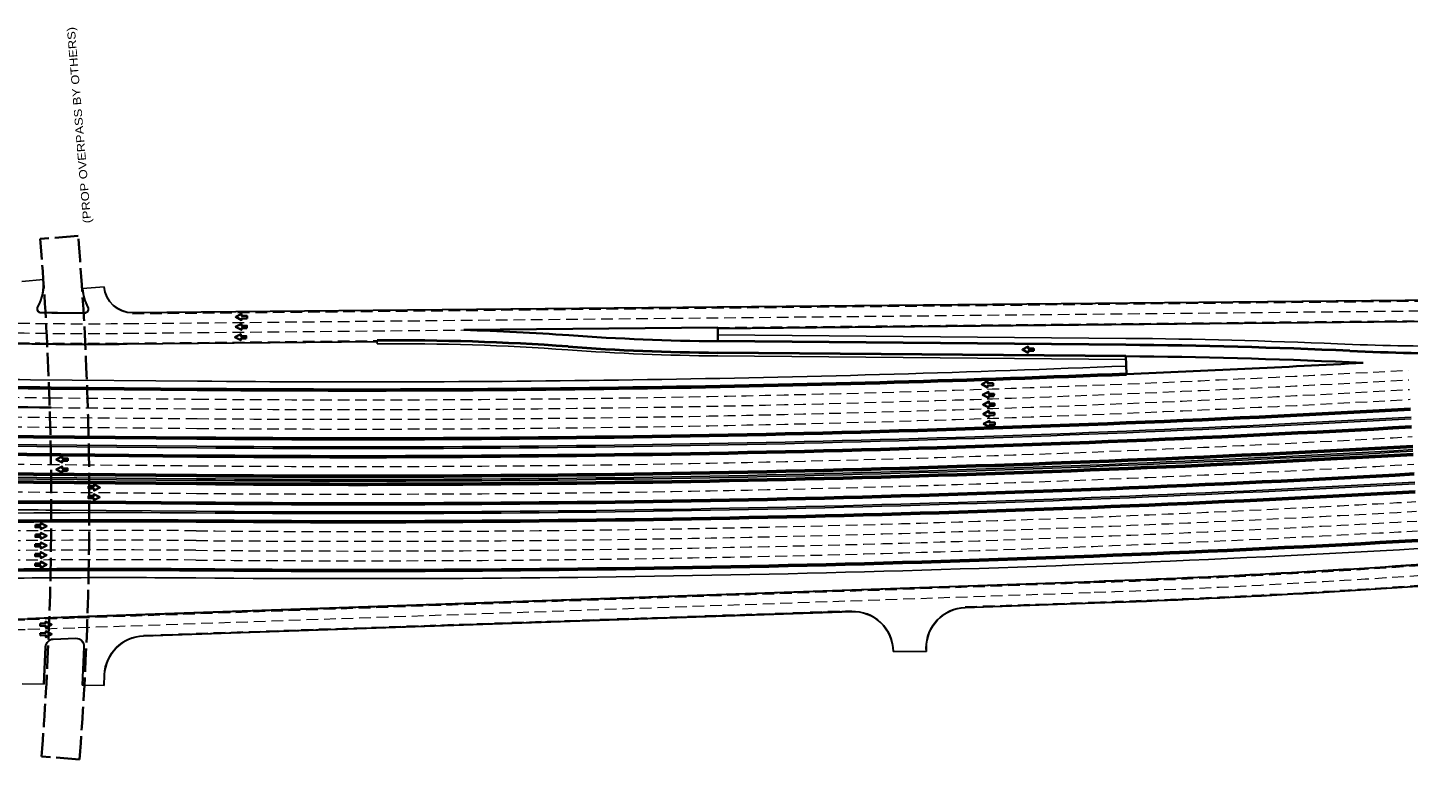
# Model space of a CAD drawing. Extents: x 2326434 to 2368642, y 6985225 to 6995090.
# Drawn here: x 2337174 to 2338872, y 6990920 to 6991821 of the extents above; entities that cross this region are included whole.
import ezdxf

# ---------------------------------------------------------------- set-up
doc = ezdxf.new("R2010")
doc.units = 0
doc.header["$LTSCALE"] = 4.8
doc.linetypes.add('LONG_DASHED', pattern=[7.5, 6, -1.5])
doc.linetypes.add('MEDIUM_DASHED', pattern=[4.5, 3, -1.5])
for name, color, linetype, lineweight in [('10', 7, 'Continuous', 35), ('20', 7, 'LONG_DASHED', 35), ('26', 7, 'Continuous', 25), ('27', 7, 'Continuous', 25), ('28', 7, 'Continuous', 25), ('30', 7, 'Continuous', 25), ('40', 7, 'Continuous', 35), ('50', 7, 'MEDIUM_DASHED', 13)]:
    doc.layers.add(name, color=color, linetype=linetype, lineweight=lineweight)

msp = doc.modelspace()

# ---------------------------------------------------------------- linework, layer by layer
at = {"layer": '10'}
for p, q in [((2337710.319, 6991448.663), (2338022.416, 6991451.725)), ((2338022.416, 6991451.725), (2338022.583, 6991434.726)), ((2338524.406, 6991416.353), (2338525.316, 6991394.372)), ((2336756.625, 6991357.064), (2337202.249, 6991353.214))]:
    msp.add_line(p, q, dxfattribs=at)
for centre, radius, start, end in [((2337631.381, 6988584.962), 2864.789, 85.83473, 88.42104), ((2338047.541, 6994299.406), 2864.789, 265.83473, 269.50083), ((2338457.973, 6983791.205), 7625.437, 87.43444, 89.50083), ((2337579.809, 7014229.636), 22854.83, 272.37101, 273.10141), ((2338946.487, 6994693.748), 3288.044, 267.43444, 267.73144), ((2337227.445, 6994241.893), 2888.789, 264.99101, 269.50502)]:
    msp.add_arc(centre, radius, start, end, dxfattribs=at)
at = {"layer": '20'}
for p, q in [((2337235.759, 6991564.563), (2337189.112, 6991560.708)), ((2337237.485, 6990920.494), (2337190.819, 6990924.099))]:
    msp.add_line(p, q, dxfattribs=at)
for radius in [4041.658, 3994.852]:
    msp.add_arc((2333207.829, 6991231.728), radius, 355.58348, 4.72371, dxfattribs=at)
at = {"layer": '26'}
for p, q in [((2337177.257, 6991387.431), (2337382.455, 6991385.658)), ((2336698.283, 6991311.566), (2337381.764, 6991305.661))]:
    msp.add_line(p, q, dxfattribs=at)
at = {"layer": '26', "lineweight": 53}
for p, q in [((2337202.696, 6991377.211), (2337382.368, 6991375.659)), ((2336698.37, 6991321.566), (2337381.85, 6991315.661))]:
    msp.add_line(p, q, dxfattribs=at)
for centre, radius, start, end in [((2337579.809, 7014229.636), 22854.83, 269.50502, 272.37101), ((2337579.809, 7014229.636), 22914.83, 269.50502, 273.23943), ((2337579.809, 7014229.636), 23016.83, 269.50502, 273.23943), ((2337281.973, 6979754.936), 11459.156, 89.50501, 93.05595), ((2337579.809, 7014229.636), 23076.83, 269.50502, 273.23943), ((2337281.973, 6979754.936), 11399.156, 89.50501, 91.1232)]:
    msp.add_arc(centre, radius, start, end, dxfattribs=at)
at = {"layer": '26'}
for centre, radius, start, end in [((2337579.809, 7014229.636), 22844.83, 269.50502, 272.37101), ((2337579.809, 7014229.636), 22924.83, 269.50502, 273.23943), ((2337579.809, 7014229.636), 23006.83, 269.50502, 273.23943), ((2337281.973, 6979754.936), 11469.156, 89.50501, 93.05595), ((2337579.809, 7014229.636), 23086.83, 269.50502, 273.23943), ((2337281.973, 6979754.936), 11389.156, 89.50501, 91.1232)]:
    msp.add_arc(centre, radius, start, end, dxfattribs=at)
at = {"layer": '27'}
for p, q in [((2337603.414, 6991435.613), (2337603.453, 6991431.614)), ((2338524.598, 6991438.352), (2338022.653, 6991442.725)), ((2338524.371, 6991412.353), (2338022.374, 6991416.727))]:
    msp.add_line(p, q, dxfattribs=at)
at = {"layer": '27', "lineweight": 40}
for p, q in [((2338524.528, 6991430.353), (2338022.583, 6991434.726)), ((2338524.406, 6991416.353), (2338022.409, 6991420.727))]:
    msp.add_line(p, q, dxfattribs=at)
for centre, radius, start, end in [((2337631.381, 6988584.962), 2850.789, 85.83473, 90.56211), ((2338047.541, 6994299.406), 2878.789, 265.83473, 269.50083), ((2338457.973, 6983791.205), 7639.437, 87.43444, 89.50083), ((2338946.487, 6994693.748), 3274.044, 267.43444, 272.71231)]:
    msp.add_arc(centre, radius, start, end, dxfattribs=at)
at = {"layer": '27'}
for centre, radius, start, end in [((2337631.381, 6988584.962), 2846.789, 85.83473, 90.56211), ((2338457.973, 6983791.205), 7647.437, 87.55123, 89.50083), ((2338924.605, 6994702.714), 3274.044, 267.55123, 272.7589), ((2338047.541, 6994299.406), 2882.789, 265.83473, 269.50083), ((2337202.006, 6994252.113), 2864.789, 265.16574, 269.50502)]:
    msp.add_arc(centre, radius, start, end, dxfattribs=at)
at = {"layer": '27', "lineweight": 53}
msp.add_arc((2337227.445, 6994241.893), 2864.789, 264.99101, 269.50502, dxfattribs=at)
at = {"layer": '28'}
for p, q in [((2337166.442, 6991508.478), (2337193.356, 6991510.64)), ((2337240.982, 6991499.57), (2337267.889, 6991501.805)), ((2337302.609, 6991470.164), (2339322.097, 6991489.977)), ((2337302.614, 6991469.664), (2339322.102, 6991489.477)), ((2338022.426, 6991450.725), (2339678.529, 6991466.973)), ((2338022.431, 6991450.225), (2339678.534, 6991466.473)), ((2337296.169, 6991431.599), (2337603.423, 6991434.613)), ((2337296.174, 6991431.099), (2337603.428, 6991434.113)), ((2337235.517, 6991096.114), (2338484.897, 6991139.471)), ((2337235.535, 6991095.614), (2338484.914, 6991138.971)), ((2338326.894, 6991107.472), (2338485.816, 6991112.987)), ((2338326.912, 6991106.972), (2338485.833, 6991112.487)), ((2337173.645, 6991093.966), (2337235.517, 6991096.114)), ((2337173.663, 6991093.467), (2337235.535, 6991095.614)), ((2337316.058, 6991072.393), (2338186.925, 6991102.614)), ((2337316.076, 6991071.893), (2338186.943, 6991102.115)), ((2337195.413, 6991058.993), (2337193.352, 6991012.849)), ((2337195.912, 6991058.97), (2337193.852, 6991012.838)), ((2337205.056, 6991068.541), (2337233.016, 6991069.511)), ((2337205.073, 6991068.041), (2337233.034, 6991069.011)), ((2337242.854, 6991059.093), (2337240.741, 6991011.783)), ((2337243.353, 6991059.071), (2337241.241, 6991011.771)), ((2338278.63, 6991057.149), (2338278.657, 6991053.28)), ((2338279.13, 6991057.181), (2338279.157, 6991053.283)), ((2338238.158, 6991052.994), (2338279.157, 6991053.283)), ((2337267.842, 6991024.653), (2337267.241, 6991011.186)), ((2337268.342, 6991024.631), (2337267.741, 6991011.175)), ((2337166.852, 6991013.445), (2337193.852, 6991012.838)), ((2337240.741, 6991011.783), (2337267.741, 6991011.175))]:
    msp.add_line(p, q, dxfattribs=at)
for centre, radius, start, end in [((2337132.053, 6991505.716), 61, 331.96281, 4.59183), ((2337132.053, 6991505.716), 61.5, 331.96281, 4.59183), ((2337302.27, 6991504.662), 61.5, 184.74992, 207.3289), ((2337302.27, 6991504.662), 61, 184.74991, 207.32889), ((2337302.27, 6991504.662), 35, 184.74991, 270.56211), ((2337302.27, 6991504.662), 34.5, 184.74991, 270.56211), ((2337190.307, 6991474.693), 5, 151.96281, 269.33301), ((2337190.307, 6991474.693), 4.5, 151.96281, 269.33301), ((2337247.526, 6996389.63), 4920.27, 269.33301, 269.95466), ((2337247.526, 6996389.63), 4919.77, 269.33301, 269.95466), ((2337243.637, 6991474.362), 5, 269.95466, 27.32889), ((2337243.637, 6991474.362), 4.5, 269.95466, 27.32889), ((2337247.526, 6996389.63), 4958.77, 268.75498, 270.56211), ((2337247.526, 6996389.63), 4958.27, 268.75498, 270.56211), ((2338087.563, 7002588.999), 11456.42, 271.98754, 274.03957), ((2338087.563, 7002588.999), 11456.92, 271.98754, 274.03957), ((2338087.563, 7002588.999), 11482.92, 271.98754, 274.03957), ((2338087.563, 7002588.999), 11483.42, 271.98754, 274.03957), ((2338328.629, 6991057.502), 50, 91.98754, 180.40427), ((2338328.629, 6991057.502), 49.5, 91.98754, 180.40427), ((2336776.311, 7002543.494), 11456.92, 271.03427, 271.98754), ((2338188.659, 6991052.645), 50, 0.40427, 91.98754), ((2338188.659, 6991052.645), 49.5, 0.40427, 91.98754), ((2337317.792, 6991022.423), 50, 91.98754, 177.44335), ((2337317.792, 6991022.423), 49.5, 91.98754, 177.44335), ((2337205.403, 6991058.547), 10, 91.98754, 177.44335), ((2337205.403, 6991058.547), 9.5, 91.98754, 177.44335), ((2337233.363, 6991059.517), 10, 357.44335, 91.98754), ((2337233.363, 6991059.517), 9.5, 357.44335, 91.98754)]:
    msp.add_arc(centre, radius, start, end, dxfattribs=at)
at = {"layer": '30'}
for p, q in [((2336475.079, 6991311.494), (2337381.746, 6991303.661)), ((2334459.068, 6991288.91), (2337381.401, 6991263.663)), ((2334468.59, 6991290.827), (2337381.418, 6991265.663)), ((2337214.805, 6991227.101), (2337381.073, 6991225.664))]:
    msp.add_line(p, q, dxfattribs=at)
at = {"layer": '30', "lineweight": 53}
for p, q in [((2334487.634, 6991294.663), (2337381.453, 6991269.663)), ((2336506.512, 6991301.222), (2337381.66, 6991293.662)), ((2334440.023, 6991285.074), (2337381.366, 6991259.663)), ((2337251.371, 6991236.785), (2337381.159, 6991235.664))]:
    msp.add_line(p, q, dxfattribs=at)
for centre, radius, start, end in [((2337579.809, 7014229.636), 22936.83, 269.50502, 273.23943), ((2337579.809, 7014229.636), 22970.83, 269.50502, 273.23943), ((2337579.809, 7014229.636), 22960.83, 269.50502, 273.23943), ((2337579.809, 7014229.636), 22994.83, 269.50502, 273.23943), ((2337201.874, 6985507.421), 5729.578, 89.50502, 92.71686)]:
    msp.add_arc(centre, radius, start, end, dxfattribs=at)
at = {"layer": '30'}
for centre, radius, start, end in [((2337579.809, 7014229.636), 22926.83, 269.50502, 273.23943), ((2337579.809, 7014229.636), 22966.83, 269.50502, 273.23943), ((2337579.809, 7014229.636), 22964.83, 269.50502, 273.23943), ((2337579.809, 7014229.636), 23004.83, 269.50502, 273.23943), ((2337165.308, 6985497.736), 5729.578, 89.50502, 92.53207)]:
    msp.add_arc(centre, radius, start, end, dxfattribs=at)
at = {"layer": '40'}
for points in [[(2337443.582, 6991462.949), (2337443.598, 6991465.95), (2337436.791, 6991465.987), (2337436.804, 6991468.424), (2337429.584, 6991464.684), (2337436.764, 6991460.866), (2337436.775, 6991462.986)], [(2337443.407, 6991450.837), (2337443.423, 6991453.837), (2337436.616, 6991453.874), (2337436.629, 6991456.311), (2337429.409, 6991452.571), (2337436.589, 6991448.754), (2337436.6, 6991450.873)], [(2337442.635, 6991438.094), (2337442.651, 6991441.095), (2337435.844, 6991441.131), (2337435.858, 6991443.569), (2337428.637, 6991439.829), (2337435.817, 6991436.011), (2337435.828, 6991438.131)], [(2338411.189, 6991422.858), (2338411.195, 6991425.859), (2338404.388, 6991425.873), (2338404.393, 6991428.31), (2338397.185, 6991424.546), (2338404.378, 6991420.752), (2338404.382, 6991422.872)], [(2338361.181, 6991380.142), (2338361.203, 6991383.143), (2338354.396, 6991383.193), (2338354.414, 6991385.631), (2338347.186, 6991381.905), (2338354.359, 6991378.073), (2338354.374, 6991380.193)], [(2338362.277, 6991367.113), (2338362.299, 6991370.113), (2338355.493, 6991370.164), (2338355.511, 6991372.601), (2338348.283, 6991368.875), (2338355.455, 6991365.043), (2338355.471, 6991367.163)], [(2338362.913, 6991355.394), (2338362.86, 6991358.394), (2338356.054, 6991358.273), (2338356.011, 6991360.71), (2338348.879, 6991356.804), (2338356.145, 6991353.154), (2338356.107, 6991355.273)], [(2338363.003, 6991343.742), (2338362.95, 6991346.742), (2338356.144, 6991346.621), (2338356.101, 6991349.058), (2338348.969, 6991345.152), (2338356.235, 6991341.502), (2338356.198, 6991343.621)], [(2338363.48, 6991331.792), (2338363.426, 6991334.793), (2338356.621, 6991334.672), (2338356.577, 6991337.109), (2338349.445, 6991333.203), (2338356.712, 6991329.552), (2338356.674, 6991331.672)], [(2337222.946, 6991287.749), (2337222.953, 6991290.75), (2337216.146, 6991290.765), (2337216.151, 6991293.202), (2337208.943, 6991289.439), (2337216.135, 6991285.645), (2337216.139, 6991287.764)], [(2337222.851, 6991275.365), (2337222.858, 6991278.365), (2337216.051, 6991278.38), (2337216.057, 6991280.818), (2337208.848, 6991277.055), (2337216.04, 6991273.26), (2337216.045, 6991275.38)], [(2337248.63, 6991256.556), (2337248.605, 6991253.555), (2337255.411, 6991253.499), (2337255.391, 6991251.062), (2337262.622, 6991254.781), (2337255.453, 6991258.619), (2337255.436, 6991256.5)], [(2337248.458, 6991244.667), (2337248.433, 6991241.666), (2337255.24, 6991241.61), (2337255.219, 6991239.173), (2337262.451, 6991242.892), (2337255.282, 6991246.73), (2337255.264, 6991244.61)], [(2337183.211, 6991209.023), (2337183.223, 6991206.022), (2337190.029, 6991206.048), (2337190.038, 6991203.61), (2337197.224, 6991207.416), (2337190.01, 6991211.168), (2337190.018, 6991209.048)], [(2337183.183, 6991197.132), (2337183.194, 6991194.131), (2337190.001, 6991194.157), (2337190.01, 6991191.72), (2337197.196, 6991195.526), (2337189.981, 6991199.277), (2337189.989, 6991197.158)], [(2337183.046, 6991173.438), (2337183.058, 6991170.437), (2337189.864, 6991170.463), (2337189.874, 6991168.026), (2337197.06, 6991171.832), (2337189.845, 6991175.583), (2337189.853, 6991173.464)], [(2337183.115, 6991185.285), (2337183.126, 6991182.284), (2337189.933, 6991182.31), (2337189.942, 6991179.873), (2337197.128, 6991183.679), (2337189.913, 6991187.43), (2337189.921, 6991185.311)], [(2337182.978, 6991161.591), (2337182.99, 6991158.59), (2337189.796, 6991158.616), (2337189.806, 6991156.179), (2337196.991, 6991159.985), (2337189.777, 6991163.737), (2337189.785, 6991161.617)], [(2337188.996, 6991087.729), (2337189.083, 6991084.729), (2337195.887, 6991084.928), (2337195.958, 6991082.492), (2337203.045, 6991086.479), (2337195.738, 6991090.046), (2337195.8, 6991087.927)], [(2337189.229, 6991075.884), (2337189.316, 6991072.884), (2337196.12, 6991073.083), (2337196.191, 6991070.647), (2337203.278, 6991074.634), (2337195.971, 6991078.201), (2337196.033, 6991076.083)]]:
    msp.add_lwpolyline(points, close=True, dxfattribs=at)
at = {"layer": '50'}
for p, q in [((2337295.924, 6991456.598), (2339678.402, 6991479.972)), ((2337302.623, 6991468.664), (2339493.864, 6991490.162)), ((2338022.416, 6991451.725), (2339678.519, 6991467.973)), ((2337296.042, 6991444.598), (2337710.319, 6991448.663)), ((2337296.16, 6991432.599), (2337603.414, 6991435.613)), ((2337202.351, 6991365.213), (2337382.265, 6991363.659)), ((2336698.577, 6991345.565), (2337382.057, 6991339.66)), ((2337202.252, 6991353.214), (2337382.161, 6991351.659)), ((2336698.474, 6991333.565), (2337381.954, 6991327.66)), ((2336399.122, 6991290.15), (2337381.556, 6991281.662)), ((2336936.844, 6991251.503), (2337381.263, 6991247.663)), ((2337235.57, 6991094.615), (2338484.949, 6991137.972)), ((2337235.986, 6991082.622), (2338485.365, 6991125.979)), ((2338326.86, 6991108.471), (2338485.781, 6991113.986)), ((2337173.697, 6991092.467), (2337235.57, 6991094.615)), ((2337316.024, 6991073.392), (2338186.891, 6991103.614)), ((2337174.114, 6991080.475), (2337235.986, 6991082.622))]:
    msp.add_line(p, q, dxfattribs=at)
for centre, radius, start, end in [((2337247.526, 6996389.63), 4945.27, 268.75498, 270.56211), ((2337247.526, 6996389.63), 4933.27, 268.75498, 270.56211), ((2337247.526, 6996389.63), 4957.27, 268.75498, 270.56211), ((2337579.809, 7014229.636), 22866.83, 269.50502, 273.23943), ((2337579.809, 7014229.636), 22878.83, 269.50502, 273.23943), ((2337227.445, 6994241.893), 2876.789, 264.99101, 269.50502), ((2337579.809, 7014229.636), 22902.83, 269.50502, 273.23943), ((2337579.809, 7014229.636), 22890.83, 269.50502, 273.23943), ((2337579.809, 7014229.636), 22948.83, 269.50502, 273.23943), ((2337579.809, 7014229.636), 22982.83, 269.50502, 273.23943), ((2337579.809, 7014229.636), 23040.83, 269.50502, 273.23943), ((2337579.809, 7014229.636), 23028.83, 269.50502, 273.23943), ((2337579.809, 7014229.636), 23052.83, 269.50502, 273.23943), ((2337281.973, 6979754.936), 11447.156, 89.50501, 93.05595), ((2337281.973, 6979754.936), 11435.156, 89.50501, 93.05595), ((2337579.809, 7014229.636), 23064.83, 269.50502, 273.23943), ((2337281.973, 6979754.936), 11423.156, 89.50501, 92.55229), ((2337281.973, 6979754.936), 11411.156, 89.50501, 91.1232), ((2338087.563, 7002588.999), 11457.92, 271.98754, 274.03957), ((2338087.563, 7002588.999), 11469.92, 271.98754, 274.03958), ((2338087.563, 7002588.999), 11481.92, 271.98754, 274.03957), ((2336776.311, 7002543.494), 11457.92, 271.03427, 271.98754), ((2336776.311, 7002543.494), 11469.92, 271.03427, 271.98754)]:
    msp.add_arc(centre, radius, start, end, dxfattribs=at)

# ---------------------------------------------------------------- texts
at = {"layer": '10', "width": 1.2}
msp.add_text('(PROP OVERPASS BY OTHERS)', height=9.843, rotation=94.795, dxfattribs=at).set_placement((2337251.905, 6991580.322))

doc.saveas('drawing.dxf')
